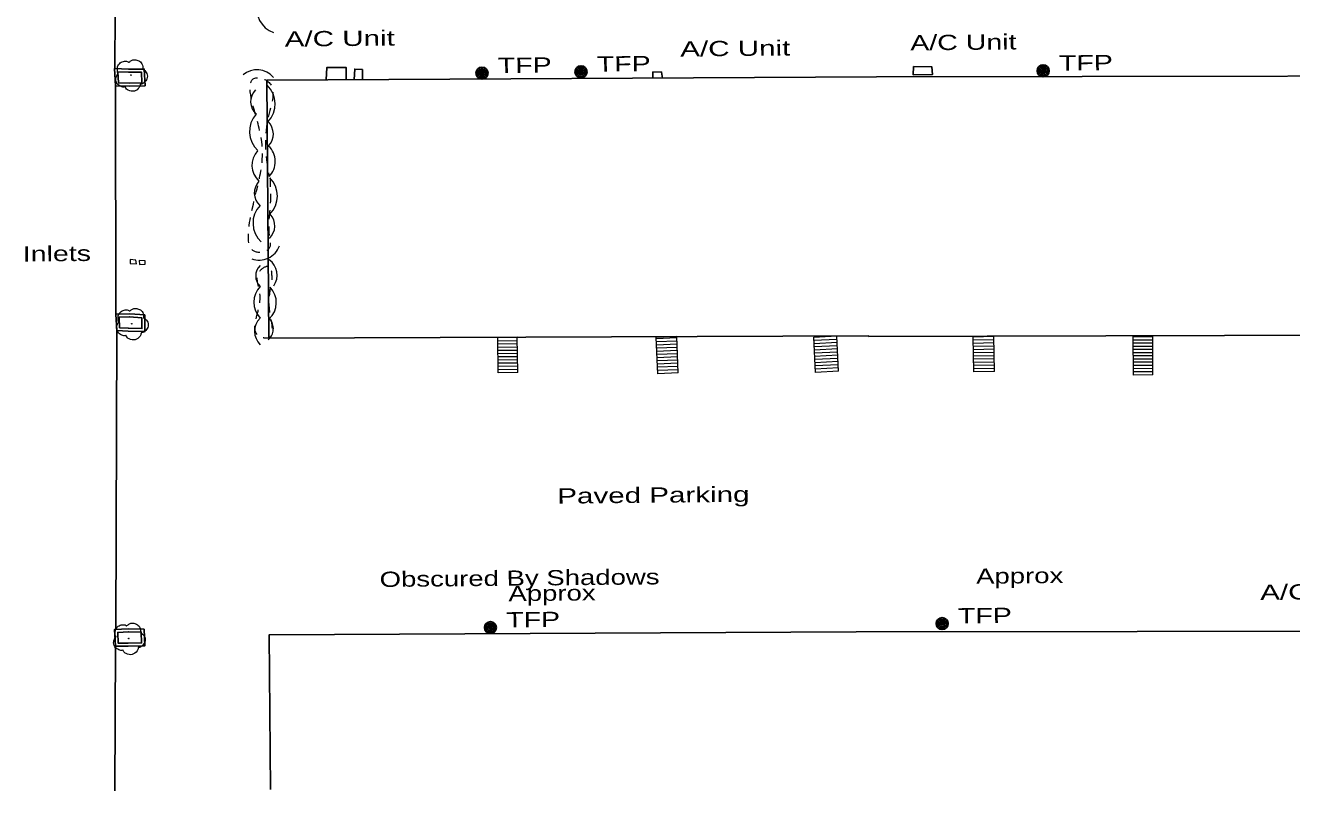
# Model space of a CAD drawing. Extents: x 2362213 to 2366494, y 6968794 to 6978110.
# Drawn here: x 2362961.8 to 2363360.6, y 6975890.3 to 6976131.3 of the extents above; entities that cross this region are included whole.
import ezdxf

# ---------------------------------------------------------------- set-up
doc = ezdxf.new("R2010")
doc.units = 0
doc.header["$LTSCALE"] = 1.9
doc.linetypes.add('SHORT_DASHED', pattern=[2.7, 1.5, -1.2])
for name, color, linetype, lineweight in [('11', 7, 'Continuous', 25), ('16', 7, 'Continuous', 13), ('2', 7, 'Continuous', 25), ('20', 7, 'Continuous', 25), ('23', 7, 'Continuous', 25), ('29', 7, 'Continuous', 13), ('9', 7, 'Continuous', 13)]:
    doc.layers.add(name, color=color, linetype=linetype, lineweight=lineweight)

msp = doc.modelspace()

# ---------------------------------------------------------------- linework, layer by layer
at = {"layer": '11'}
for points in [[(2363229.871, 6976115.051), (2363037.893, 6976114.063), (2363038.527, 6976032.745), (2363227.339, 6976033.493), (2363227.331, 6976033.273)], [(2363229.871, 6976115.051), (2363488.78, 6976115.466), (2363488.976, 6976033.995), (2363227.331, 6976033.273)], [(2363223.446, 6975940.272), (2363038.616, 6975939.412), (2363039.011, 6975890.633)], [(2363223.446, 6975940.272), (2363488.935, 6975940.66), (2363488.843, 6975890.407)]]:
    msp.add_lwpolyline(points, dxfattribs=at)
at = {"layer": '16'}
for p, q in [((2363116.687, 6976033.059), (2363110.558, 6976032.971)), ((2363110.724, 6976021.862), (2363110.558, 6976032.971)), ((2363116.698, 6976032.95), (2363110.569, 6976032.861)), ((2363116.707, 6976031.95), (2363110.579, 6976031.861)), ((2363116.727, 6976030.95), (2363110.599, 6976030.861)), ((2363116.853, 6976021.951), (2363116.687, 6976033.059)), ((2363166.927, 6976033.258), (2363160.469, 6976032.996)), ((2363160.928, 6976021.6), (2363160.469, 6976032.996)), ((2363166.941, 6976032.848), (2363160.483, 6976032.586)), ((2363166.981, 6976031.858), (2363160.523, 6976031.597)), ((2363167.02, 6976030.859), (2363160.562, 6976030.597)), ((2363167.386, 6976021.862), (2363166.927, 6976033.258)), ((2363217.319, 6976033.458), (2363210.061, 6976033.089)), ((2363210.616, 6976022.023), (2363210.061, 6976033.089)), ((2363217.319, 6976033.378), (2363210.062, 6976033.009)), ((2363217.369, 6976032.378), (2363210.111, 6976032.009)), ((2363217.418, 6976031.379), (2363210.161, 6976031.009)), ((2363217.468, 6976030.379), (2363210.21, 6976030.01)), ((2363217.874, 6976022.392), (2363217.319, 6976033.458)), ((2363266.762, 6976033.379), (2363260.283, 6976033.247)), ((2363260.508, 6976022.138), (2363260.283, 6976033.247)), ((2363266.763, 6976033.269), (2363260.284, 6976033.137)), ((2363266.782, 6976032.269), (2363260.303, 6976032.137)), ((2363266.802, 6976031.269), (2363260.323, 6976031.137)), ((2363266.821, 6976030.269), (2363260.342, 6976030.137)), ((2363266.987, 6976022.27), (2363266.762, 6976033.379)), ((2363316.833, 6976033.515), (2363310.673, 6976033.487)), ((2363310.74, 6976021.177), (2363310.673, 6976033.487)), ((2363316.845, 6976032.205), (2363310.685, 6976032.177)), ((2363316.846, 6976033.205), (2363310.686, 6976033.177)), ((2363316.854, 6976030.205), (2363310.694, 6976030.177)), ((2363316.855, 6976031.205), (2363310.695, 6976031.177)), ((2363316.9, 6976021.205), (2363316.833, 6976033.515)), ((2363116.737, 6976029.95), (2363110.608, 6976029.861)), ((2363116.756, 6976028.95), (2363110.628, 6976028.862)), ((2363116.766, 6976027.95), (2363110.637, 6976027.862)), ((2363116.785, 6976026.95), (2363110.657, 6976026.862)), ((2363167.06, 6976029.859), (2363160.602, 6976029.597)), ((2363167.099, 6976028.859), (2363160.641, 6976028.598)), ((2363167.139, 6976027.86), (2363160.681, 6976027.598)), ((2363167.188, 6976026.86), (2363160.73, 6976026.599)), ((2363217.518, 6976029.379), (2363210.26, 6976029.01)), ((2363217.567, 6976028.38), (2363210.309, 6976028.011)), ((2363217.616, 6976027.39), (2363210.359, 6976027.021)), ((2363217.666, 6976026.391), (2363210.408, 6976026.022)), ((2363266.841, 6976029.269), (2363260.362, 6976029.137)), ((2363266.87, 6976028.269), (2363260.391, 6976028.138)), ((2363266.89, 6976027.269), (2363260.411, 6976027.138)), ((2363266.909, 6976026.27), (2363260.43, 6976026.138)), ((2363316.863, 6976028.205), (2363310.703, 6976028.177)), ((2363316.864, 6976029.205), (2363310.704, 6976029.177)), ((2363316.872, 6976026.205), (2363310.712, 6976026.177)), ((2363316.873, 6976027.205), (2363310.713, 6976027.177)), ((2363116.795, 6976025.95), (2363110.666, 6976025.862)), ((2363116.814, 6976024.95), (2363110.686, 6976024.862)), ((2363116.824, 6976023.95), (2363110.695, 6976023.862)), ((2363116.843, 6976022.95), (2363110.715, 6976022.862)), ((2363167.228, 6976025.86), (2363160.77, 6976025.599)), ((2363167.267, 6976024.861), (2363160.809, 6976024.599)), ((2363167.307, 6976023.861), (2363160.849, 6976023.6)), ((2363167.346, 6976022.861), (2363160.888, 6976022.6)), ((2363217.725, 6976025.391), (2363210.468, 6976025.022)), ((2363217.775, 6976024.392), (2363210.517, 6976024.023)), ((2363217.825, 6976023.392), (2363210.567, 6976023.023)), ((2363217.874, 6976022.392), (2363210.616, 6976022.023)), ((2363266.929, 6976025.27), (2363260.45, 6976025.138)), ((2363266.948, 6976024.27), (2363260.469, 6976024.138)), ((2363266.968, 6976023.27), (2363260.489, 6976023.138)), ((2363266.987, 6976022.27), (2363260.508, 6976022.138)), ((2363316.881, 6976024.205), (2363310.721, 6976024.177)), ((2363316.882, 6976025.205), (2363310.722, 6976025.177)), ((2363316.89, 6976022.205), (2363310.73, 6976022.177)), ((2363316.891, 6976023.205), (2363310.731, 6976023.177)), ((2363116.853, 6976021.951), (2363110.724, 6976021.862)), ((2363167.386, 6976021.862), (2363160.928, 6976021.6)), ((2363316.9, 6976021.205), (2363310.74, 6976021.177))]:
    msp.add_line(p, q, dxfattribs=at)
at = {"layer": '2'}
for p, q in [((2362990.055, 6976135.558), (2362990.016, 6976117.657)), ((2362990.207, 6976112.229), (2362990.322, 6976040.296)), ((2362990.591, 6976035.148), (2362990.327, 6975941.081)), ((2362990.168, 6975935.75), (2362989.951, 6975890.286))]:
    msp.add_line(p, q, dxfattribs=at)
for points in [[(2362994.288, 6976117.528), (2362989.936, 6976117.656), (2362990.207, 6976112.229), (2362994.5, 6976112.1)], [(2362994.257, 6976116.567), (2362990.945, 6976116.666), (2362991.118, 6976113.157), (2362994.531, 6976113.06)], [(2362994.461, 6976113.059), (2362998.498, 6976113.218), (2362998.346, 6976116.556), (2362994.287, 6976116.568)], [(2362994.5, 6976112.1), (2362999.497, 6976112.297), (2362999.267, 6976117.515), (2362994.288, 6976117.528)], [(2362994.702, 6976040.448), (2362990.322, 6976040.296), (2362990.591, 6976035.148), (2362994.214, 6976034.942)], [(2362994.731, 6976039.488), (2362991.331, 6976039.366), (2362991.503, 6976036.057), (2362994.265, 6976035.903)], [(2362994.174, 6976034.942), (2362999.465, 6976034.832), (2362999.435, 6976040.083), (2362994.702, 6976040.448)], [(2362994.195, 6976035.902), (2362998.495, 6976035.813), (2362998.483, 6976039.194), (2362994.631, 6976039.487)], [(2362994.246, 6975941.258), (2362989.897, 6975941.067), (2362990.168, 6975935.75), (2362994.239, 6975935.789)], [(2362994.286, 6975940.299), (2362990.906, 6975940.146), (2362991.079, 6975936.719), (2362994.229, 6975936.749)], [(2362994.229, 6975936.749), (2362998.428, 6975936.809), (2362998.296, 6975940.207), (2362994.226, 6975940.298)], [(2362994.239, 6975935.789), (2362999.427, 6975935.858), (2362999.217, 6975941.146), (2362994.246, 6975941.258)]]:
    msp.add_lwpolyline(points, dxfattribs=at)
at = {"layer": '20'}
for centre, radius in [((2363105.605, 6976116.218), 1.9), ((2363136.782, 6976116.665), 1.9), ((2363136.782, 6976116.665), 1.442), ((2363282.306, 6976116.99), 1.9), ((2363282.306, 6976116.99), 1.442), ((2363282.306, 6976116.99), 0.973), ((2363105.605, 6976116.218), 1.442), ((2363105.605, 6976116.218), 0.973), ((2363105.605, 6976116.218), 0.539), ((2363105.605, 6976116.218), 0.192), ((2363136.782, 6976116.665), 0.973), ((2363136.782, 6976116.665), 0.539), ((2363136.782, 6976116.665), 0.192), ((2363282.306, 6976116.99), 0.539), ((2363282.306, 6976116.99), 0.192), ((2363108.248, 6975941.635), 1.9), ((2363108.248, 6975941.635), 1.442), ((2363108.248, 6975941.635), 0.973), ((2363250.502, 6975942.899), 1.9), ((2363250.502, 6975942.899), 1.442), ((2363250.502, 6975942.899), 0.973), ((2363250.502, 6975942.899), 0.539), ((2363250.502, 6975942.899), 0.192), ((2363108.248, 6975941.635), 0.539), ((2363108.248, 6975941.635), 0.192)]:
    msp.add_circle(centre, radius, dxfattribs=at)
at = {"layer": '23'}
for points in [[(2363056.532, 6976114.16), (2363056.745, 6976118.013), (2363062.877, 6976117.981), (2363062.873, 6976114.191)], [(2363065.372, 6976114.204), (2363065.52, 6976117.546), (2363067.962, 6976117.389), (2363068.012, 6976114.22)], [(2363159.432, 6976114.69), (2363159.433, 6976116.64), (2363162.154, 6976116.556), (2363162.401, 6976114.708)]]:
    msp.add_lwpolyline(points, dxfattribs=at)
msp.add_lwpolyline([(2363241.512, 6976118.302), (2363241.346, 6976115.76), (2363247.475, 6976115.859), (2363247.293, 6976118.227)], close=True, dxfattribs=at)
at = {"layer": '29'}
for centre in [(2362995.055, 6976115.625), (2362995.311, 6976037.324), (2362994.375, 6975938.2)]:
    msp.add_circle(centre, 0.1, dxfattribs=at)
for centre, radius, start, end in [((2363042.419, 6976136.203), 7.604, 160.97716, 250.97716), ((2363034.744, 6976110.53), 6.795, 40.27147, 130.27147), ((2363038.19, 6976107.227), 5.43, 136.5623, 226.5623), ((2363032.311, 6976106.594), 8.15, 315.88622, 45.88622), ((2363040.541, 6976097.858), 8.15, 137.57508, 227.57508), ((2363034.486, 6976097.078), 5.43, 316.10625, 46.10625), ((2363039.97, 6976087.244), 6.795, 137.57436, 227.57436), ((2363033.693, 6976088.392), 6.795, 316.11395, 46.11395), ((2363039.344, 6976078.485), 5.43, 136.77521, 226.77521), ((2363033.044, 6976077.545), 8.15, 315.05957, 45.05957), ((2363041.648, 6976069.02), 8.15, 136.79578, 226.79578), ((2363034.926, 6976068.131), 5.43, 313.3154, 43.3154), ((2363035.456, 6976064.168), 6.795, 249.74763, 339.74763), ((2363039.067, 6976052.36), 4.718, 134.66521, 224.66521), ((2363035.188, 6976052.634), 5.904, 324.91279, 54.91279), ((2363040.798, 6976044.097), 7.081, 135.01733, 225.01733), ((2363033.766, 6976043.96), 7.081, 313.51736, 43.51736), ((2363039.912, 6976034.932), 5.904, 135.27939, 225.27939), ((2363035.188, 6976035.795), 4.718, 310.825, 40.825)]:
    msp.add_arc(centre, radius, start, end, dxfattribs=at)
for points in [[(2362991.09, 6976116.197), (2362991.109, 6976116.207), (2362991.029, 6976116.277), (2362990.793, 6976116.904), (2362990.831, 6976118.185), (2362991.718, 6976119.483), (2362993.024, 6976119.966), (2362994.147, 6976119.776), (2362994.378, 6976119.649), (2362994.448, 6976119.649), (2362994.497, 6976119.69), (2362994.845, 6976119.983), (2362995.709, 6976120.431), (2362996.92, 6976120.363), (2362998.036, 6976119.774), (2362998.769, 6976118.35), (2362998.778, 6976117.49)], [(2362998.767, 6976117.51), (2362999.908, 6976116.451), (2363000.193, 6976114.864), (2362999.485, 6976113.537), (2362998.83, 6976112.991), (2362998.162, 6976112.774), (2362998.013, 6976112.763), (2362997.994, 6976112.653), (2362997.672, 6976111.75), (2362996.133, 6976110.585), (2362994.241, 6976110.867), (2362993.342, 6976111.808), (2362993.271, 6976111.938), (2362993.151, 6976111.917), (2362991.939, 6976112.035), (2362990.67, 6976113.033), (2362990.324, 6976114.67), (2362990.694, 6976115.693), (2362991.02, 6976116.137), (2362991.09, 6976116.187)], [(2362991.345, 6976037.895), (2362991.365, 6976037.906), (2362991.284, 6976037.976), (2362991.048, 6976038.603), (2362991.086, 6976039.884), (2362991.974, 6976041.182), (2362993.28, 6976041.665), (2362994.402, 6976041.475), (2362994.633, 6976041.348), (2362994.703, 6976041.348), (2362994.753, 6976041.389), (2362995.1, 6976041.682), (2362995.966, 6976042.13), (2362997.176, 6976042.062), (2362998.291, 6976041.472), (2362999.025, 6976040.049), (2362999.033, 6976039.189)], [(2362999.023, 6976039.209), (2363000.163, 6976038.15), (2363000.448, 6976036.562), (2362999.741, 6976035.235), (2362999.086, 6976034.689), (2362998.418, 6976034.472), (2362998.268, 6976034.461), (2362998.249, 6976034.351), (2362997.928, 6976033.448), (2362996.39, 6976032.284), (2362994.497, 6976032.565), (2362993.598, 6976033.506), (2362993.527, 6976033.636), (2362993.407, 6976033.615), (2362992.195, 6976033.733), (2362990.925, 6976034.731), (2362990.58, 6976036.368), (2362990.95, 6976037.391), (2362991.276, 6976037.834), (2362991.345, 6976037.885)], [(2362990.409, 6975938.773), (2362990.429, 6975938.783), (2362990.348, 6975938.852), (2362990.112, 6975939.48), (2362990.15, 6975940.759), (2362991.038, 6975942.058), (2362992.343, 6975942.54), (2362993.466, 6975942.351), (2362993.697, 6975942.223), (2362993.767, 6975942.224), (2362993.817, 6975942.264), (2362994.164, 6975942.558), (2362995.03, 6975943.006), (2362996.241, 6975942.937), (2362997.355, 6975942.348), (2362998.089, 6975940.925), (2362998.097, 6975940.065)], [(2362998.087, 6975940.085), (2362999.227, 6975939.027), (2362999.512, 6975937.439), (2362998.805, 6975936.113), (2362998.15, 6975935.566), (2362997.482, 6975935.35), (2362997.333, 6975935.338), (2362997.314, 6975935.228), (2362996.993, 6975934.325), (2362995.454, 6975933.16), (2362993.561, 6975933.442), (2362992.661, 6975934.384), (2362992.59, 6975934.513), (2362992.47, 6975934.492), (2362991.259, 6975934.611), (2362989.989, 6975935.609), (2362989.644, 6975937.245), (2362990.014, 6975938.269), (2362990.34, 6975938.712), (2362990.409, 6975938.763)]]:
    msp.add_spline(points, degree=3, dxfattribs=at)
at = {"layer": '29', "linetype": 'SHORT_DASHED'}
for points in [[(2363038.856, 6976083.321), (2363038.882, 6976074.31), (2363038.653, 6976064.698), (2363038.509, 6976060.936), (2363036.098, 6976059.852), (2363035.393, 6976082.488), (2363034.492, 6976102.52), (2363034.365, 6976114.729), (2363038.036, 6976113.724), (2363038.218, 6976101.965), (2363038.572, 6976083.698)], [(2363038.944, 6976048.84), (2363038.752, 6976040.658), (2363038.306, 6976032.853), (2363035.762, 6976033.188), (2363035.728, 6976046.169), (2363035.753, 6976054.07), (2363038.612, 6976055.377), (2363039.355, 6976052.954), (2363039.291, 6976049.193)]]:
    msp.add_spline(points, degree=3, dxfattribs=at)
at = {"layer": '9'}
for points in [[(2362994.799, 6976057.609), (2362994.851, 6976056.319), (2362996.771, 6976056.218), (2362996.57, 6976057.366)], [(2362997.651, 6976057.246), (2362997.743, 6976055.987), (2362999.593, 6976056.064), (2362999.532, 6976057.144)]]:
    msp.add_lwpolyline(points, close=True, dxfattribs=at)

# ---------------------------------------------------------------- texts
at = {"layer": '2', "width": 1.45}
msp.add_text('Paved Parking', height=4.8, rotation=0.546, dxfattribs=at).set_placement((2363129.337, 6975980.678))
at = {"layer": '20'}
for s, width, p in [('  TFP', 1.4, (2363282.306, 6976116.99)), ('  TFP', 1.4, (2363105.606, 6976116.218)), ('  TFP', 1.4, (2363136.782, 6976116.665)), ('Obscured By Shadows', 1.35, (2363073.394, 6975954.424)), ('Approx', 1.35, (2363261.214, 6975955.422)), ('Approx', 1.35, (2363113.948, 6975949.95)), ('  TFP', 1.4, (2363108.248, 6975941.634)), ('  TFP', 1.4, (2363250.502, 6975942.899))]:
    msp.add_text(s, height=4.8, rotation=0.546, dxfattribs=dict(at, width=width)).set_placement(p)
at = {"layer": '23'}
for s, width, p in [('A/C Unit', 1.45, (2363043.512, 6976124.597)), ('A/C Unit', 1.45, (2363168.067, 6976121.473)), ('A/C Unit ', 1.4, (2363240.483, 6976123.402)), ('A/C Units', 1.45, (2363350.676, 6975950.374))]:
    msp.add_text(s, height=4.8, rotation=0.546, dxfattribs=dict(at, width=width)).set_placement(p)
at = {"layer": '9', "width": 1.4}
msp.add_text('Inlets', height=4.8, rotation=0.546, dxfattribs=at).set_placement((2362961.023, 6976056.907))

doc.saveas('drawing.dxf')
